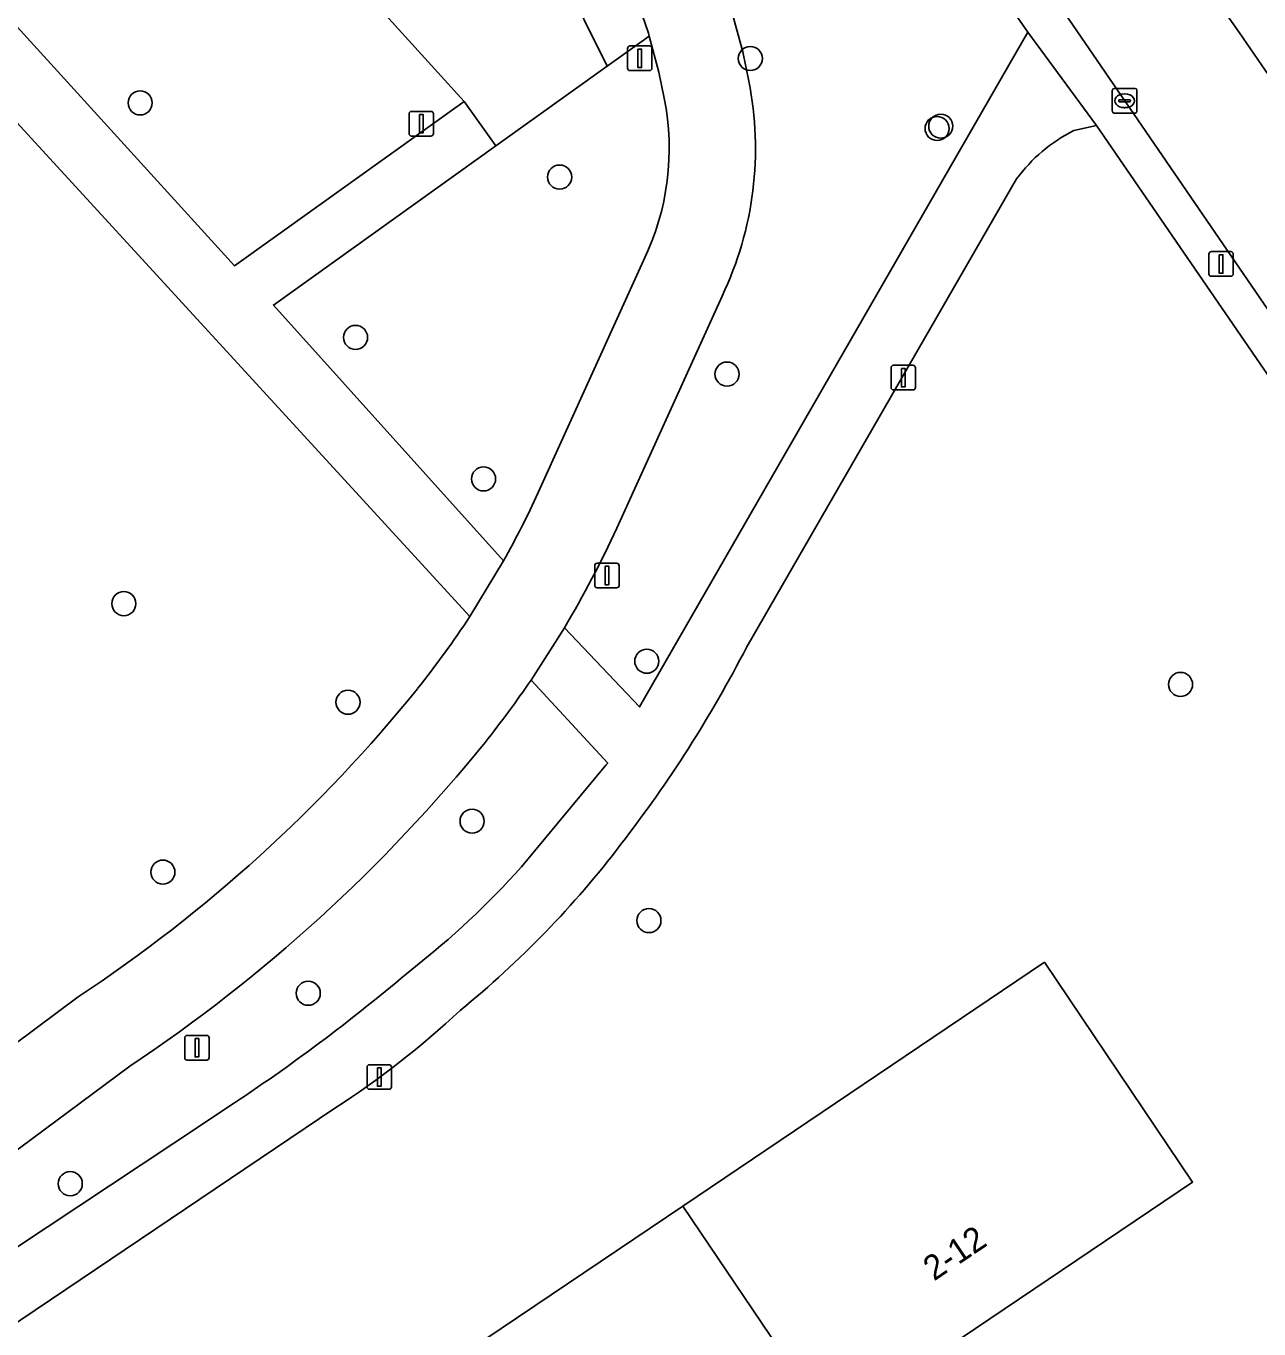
# Model space of a CAD drawing. Extents: x 157445 to 158888, y 383061 to 384688.
# Drawn here: x 158011.8 to 158061.8, y 383792.9 to 383845.7 of the extents above; entities that cross this region are included whole.
import ezdxf

# ---------------------------------------------------------------- set-up
doc = ezdxf.new("R2010")
doc.units = 0
for name, color, linetype in [('IMGEO_Boom', 7, 'Continuous'), ('IMGEO_Erf', 7, 'Continuous'), ('IMGEO_Fietspad_gesloten', 7, 'Continuous'), ('IMGEO_Groenvoorziening', 7, 'Continuous'), ('IMGEO_Kolk', 7, 'Continuous'), ('IMGEO_Lichtmast', 7, 'Continuous'), ('IMGEO_Pand', 7, 'Continuous'), ('IMGEO_Pand_nummerreeks', 7, 'Continuous'), ('IMGEO_Parkeervlak_halfverhard', 7, 'Continuous'), ('IMGEO_Rijbaan_lokaal_open', 7, 'Continuous'), ('IMGEO_Verkeersbordpaal', 7, 'Continuous'), ('IMGEO_Voetpad_halfverhard', 7, 'Continuous'), ('IMGEO_Voetpad_open', 7, 'Continuous')]:
    doc.layers.add(name, color=color, linetype=linetype)

msp = doc.modelspace()

# ---------------------------------------------------------------- linework, layer by layer
at = {"layer": 'IMGEO_Boom'}
for centre in [(158041.174, 383844.421), (158016.406, 383842.618), (158048.756, 383841.58), (158048.904, 383841.675), (158033.433, 383839.609), (158025.148, 383833.101), (158040.228, 383831.612), (158030.344, 383827.358), (158015.742, 383822.296), (158036.97, 383819.96), (158058.638, 383819.017), (158024.842, 383818.296), (158029.879, 383813.467), (158017.327, 383811.399), (158037.058, 383809.432), (158023.229, 383806.483), (158013.568, 383798.755)]:
    msp.add_circle(centre, 0.489, dxfattribs=at)
at = {"layer": 'IMGEO_Erf'}
for points in [[(158060.03, 383782.536), (158082.832, 383758.412), (158085.424, 383755.713), (158088.408, 383752.514), (158088.915, 383752.071), (158105.231, 383764.526), (158106, 383767.404), (158102.476, 383772.768), (158100.515, 383775.638), (158094.613, 383784.183), (158087.372, 383794.797), (158083.723, 383800.172), (158081.57, 383803.343), (158055.225, 383841.708), (158054.299, 383841.496)], [(158051.984, 383839.533), (158041.029, 383820.543)], [(158024.305, 383801.814), (158000, 383785.453), (157999.153, 383784.533), (157998.291, 383783.202)]]:
    msp.add_lwpolyline(points, dxfattribs=at)
msp.add_lwpolyline([(158015.062, 383769.115), (158009.046, 383778.039), (158023.723, 383787.933), (158038.433, 383797.849), (158053.11, 383807.743), (158059.126, 383798.819), (158044.449, 383788.925), (158029.739, 383779.009)], close=True, dxfattribs=at)
for centre, radius, start, end in [((158057.249, 383835.671), 6.53, 116.8567, 143.7357), ((157994.906, 383844.306), 51.884, 322.2325, 332.7419), ((158004.267, 383836.643), 39.793, 309.1569, 322.6997), ((158004.616, 383832.279), 36.274, 302.8736, 313.085)]:
    msp.add_arc(centre, radius, start, end, dxfattribs=at)
at = {"layer": 'IMGEO_Fietspad_gesloten'}
for points in [[(158041.113, 383843.504), (158040.866, 383844.685), (158040.388, 383846.467), (158038.631, 383851.59), (158038.302, 383852.55), (158037.804, 383854.078), (158037.479, 383855.23), (158037.196, 383856.757), (158036.877, 383858.474)], [(158033.429, 383857.768), (158034.07, 383854.425), (158034.435, 383853.129), (158034.991, 383851.415), (158035.77, 383849.143), (158037.038, 383845.445), (158037.07, 383845.326), (158037.46, 383843.872), (158037.681, 383842.817)], [(158036.837, 383836.222), (158032.565, 383826.808)], [(158035.752, 383825.362), (158040.026, 383834.777)], [(158031.155, 383824.033), (158029.788, 383821.778)], [(158032.271, 383819.193), (158033.627, 383821.318)], [(158013.887, 383806.337), (158007.796, 383801.81), (158004.921, 383799.673), (158000.029, 383796.035)], [(158002.118, 383793.226), (158007.009, 383796.864), (158015.982, 383803.527)]]:
    msp.add_lwpolyline(points, dxfattribs=at)
for centre, radius, start, end in [((158027.468, 383840.772), 13.916, 334.4792, 11.3208), ((158027.462, 383840.773), 10.421, 334.105, 11.3093), ((157997.631, 383842.812), 38.426, 330.7432, 335.3858), ((157997.392, 383842.939), 42.195, 329.1763, 335.3826), ((157997.521, 383842.868), 38.547, 321.4497, 326.8308), ((157997.9, 383842.601), 41.585, 321.4129, 325.7442), ((157980.301, 383857.187), 60.941, 303.44446, 321.01097), ((157980.342, 383857.142), 64.38, 303.61367, 321.04315)]:
    msp.add_arc(centre, radius, start, end, dxfattribs=at)
at = {"layer": 'IMGEO_Groenvoorziening'}
for points in [[(157947.808, 383908.446), (157904.241, 383852.492), (157897.07, 383843.386), (157895.489, 383841.379), (157893.132, 383838.504), (157893.585, 383835.721), (157894.56, 383834.399), (157906.358, 383817.738), (157931.737, 383782.008), (157938.042, 383786.453), (157940.085, 383787.894), (157959.052, 383779.967), (157966.816, 383785.159), (157989.251, 383803.05), (157991.638, 383803.565), (157993.23, 383803.909), (158000, 383802.934), (158007.796, 383801.81), (158013.887, 383806.337)], [(158052.445, 383845.49), (158047.404, 383852.735), (158045.178, 383856.038), (158038.631, 383851.59), (158040.388, 383846.467), (158040.866, 383844.685), (158041.113, 383843.504)], [(158029.788, 383821.778), (158000, 383854.238)], [(158033.627, 383821.318), (158036.68, 383818.102), (158052.445, 383845.49)], [(158037.681, 383842.817), (158037.46, 383843.872), (158037.07, 383845.326), (158035.363, 383844.105), (158030.845, 383840.874), (158021.815, 383834.415), (158031.155, 383824.033)], [(158032.565, 383826.808), (158036.837, 383836.222)], [(158040.026, 383834.777), (158035.752, 383825.362)], [(158031.889, 383811.619), (158035.303, 383815.741), (158035.385, 383815.817), (158032.271, 383819.193)], [(158015.982, 383803.527), (158007.009, 383796.864), (158010.08, 383795.309), (158017.731, 383800.376), (158020.24, 383802.038)]]:
    msp.add_lwpolyline(points, dxfattribs=at)
for points in [[(158029.555, 383842.669), (158000, 383875.224), (157994.843, 383880.905), (157992.039, 383878.385), (157986.327, 383873.253), (158000, 383858.247), (158020.237, 383836.007)], [(158035.77, 383849.143), (158034.406, 383848.41), (158033.481, 383847.913), (158035.363, 383844.105), (158037.07, 383845.326), (158037.038, 383845.445)]]:
    msp.add_lwpolyline(points, close=True, dxfattribs=at)
for centre, radius, start, end in [((158027.468, 383840.772), 13.916, 334.4792, 11.3208), ((158027.462, 383840.773), 10.421, 334.105, 11.3093), ((157997.631, 383842.812), 38.426, 330.7432, 335.3858), ((157997.392, 383842.939), 42.195, 329.1763, 335.3826), ((157997.521, 383842.868), 38.547, 321.4497, 326.8308), ((157997.9, 383842.601), 41.585, 321.4129, 325.7442), ((157980.301, 383857.187), 60.941, 303.44446, 321.01097), ((157980.342, 383857.142), 64.38, 303.61367, 321.04315), ((158006.732, 383834.076), 33.722, 307.8632, 318.2455), ((157978.135, 383865.426), 76.097, 303.59394, 310.37501)]:
    msp.add_arc(centre, radius, start, end, dxfattribs=at)
at = {"layer": 'IMGEO_Kolk'}
for p, q in [((158055.868, 383842.279), (158055.868, 383843.131)), ((158055.943, 383843.205), (158056.795, 383843.205)), ((158056.356, 383842.985), (158056.381, 383842.985)), ((158056.869, 383843.131), (158056.869, 383842.279)), ((158056.127, 383842.699), (158056.127, 383842.711)), ((158056.565, 383842.662), (158056.167, 383842.662)), ((158056.17, 383842.748), (158056.568, 383842.748)), ((158056.379, 383842.425), (158056.354, 383842.425)), ((158056.611, 383842.711), (158056.611, 383842.699)), ((158056.795, 383842.205), (158055.943, 383842.205))]:
    msp.add_line(p, q, dxfattribs=at)
for points in [[(158055.868, 383842.279), (158055.868, 383843.131)], [(158055.943, 383843.205), (158056.795, 383843.205)], [(158056.869, 383843.131), (158056.869, 383842.279)], [(158056.795, 383842.205), (158055.943, 383842.205)]]:
    msp.add_lwpolyline(points, dxfattribs=at)
for centre, radius, start, end in [((158055.945, 383843.129), 0.0765, 91.552, 178.448), ((158055.945, 383843.129), 0.0765, 91.552, 178.448), ((158056.793, 383843.129), 0.0765, 1.552, 88.448), ((158056.793, 383843.129), 0.0765, 1.552, 88.448), ((158055.945, 383842.281), 0.0765, 181.552, 268.448), ((158055.945, 383842.281), 0.0765, 181.552, 268.448), ((158056.167, 383842.708), 0.0403, 85.8775, 175.7526), ((158056.164, 383842.698), 0.0366, 178.938, 274.7102), ((158056.568, 383842.705), 0.043, 264.8664, 352.4533), ((158056.572, 383842.71), 0.0386, 1.7309, 96.639), ((158056.793, 383842.281), 0.0765, 271.552, 358.448), ((158056.793, 383842.281), 0.0765, 271.552, 358.448)]:
    msp.add_arc(centre, radius, start, end, dxfattribs=at)
for centre, major_axis, ratio, start_param, end_param in [((158056.355, 383842.705), (-0.387, 0.002), 0.722429, 4.712389, 7.853982), ((158056.38, 383842.705), (-0.39, 0.002), 0.717154, 1.570796, 4.712389)]:
    msp.add_ellipse(centre, major_axis=major_axis, ratio=ratio, start_param=start_param, end_param=end_param, dxfattribs=at)
at = {"layer": 'IMGEO_Lichtmast'}
for p, q in [((158036.289, 383844.93), (158037.079, 383844.93)), ((158037.079, 383844.93), (158036.289, 383844.93)), ((158036.189, 383844.03), (158036.189, 383844.83)), ((158036.189, 383844.83), (158036.189, 383844.03)), ((158037.179, 383844.83), (158037.179, 383844.03)), ((158037.179, 383844.03), (158037.179, 383844.83)), ((158037.079, 383843.93), (158036.289, 383843.93)), ((158036.289, 383843.93), (158037.079, 383843.93)), ((158059.79, 383835.683), (158059.79, 383836.483)), ((158059.79, 383836.483), (158059.79, 383835.683)), ((158059.89, 383836.583), (158060.68, 383836.583)), ((158060.68, 383836.583), (158059.89, 383836.583)), ((158060.78, 383836.483), (158060.78, 383835.683)), ((158060.78, 383835.683), (158060.78, 383836.483)), ((158060.68, 383835.583), (158059.89, 383835.583)), ((158059.89, 383835.583), (158060.68, 383835.583)), ((158046.886, 383831.069), (158046.886, 383831.869)), ((158046.886, 383831.869), (158046.886, 383831.069)), ((158046.986, 383831.969), (158047.776, 383831.969)), ((158047.776, 383831.969), (158046.986, 383831.969)), ((158047.876, 383831.869), (158047.876, 383831.069)), ((158047.876, 383831.069), (158047.876, 383831.869)), ((158047.776, 383830.969), (158046.986, 383830.969)), ((158046.986, 383830.969), (158047.776, 383830.969)), ((158034.857, 383823.037), (158034.857, 383823.837)), ((158034.857, 383823.837), (158034.857, 383823.037)), ((158034.957, 383823.937), (158035.747, 383823.937)), ((158035.747, 383823.937), (158034.957, 383823.937)), ((158035.847, 383823.837), (158035.847, 383823.037)), ((158035.847, 383823.037), (158035.847, 383823.837)), ((158035.747, 383822.937), (158034.957, 383822.937)), ((158034.957, 383822.937), (158035.747, 383822.937)), ((158018.316, 383804.772), (158019.106, 383804.772)), ((158019.106, 383804.772), (158018.316, 383804.772)), ((158018.216, 383803.872), (158018.216, 383804.672)), ((158018.216, 383804.672), (158018.216, 383803.872)), ((158019.206, 383804.672), (158019.206, 383803.872)), ((158019.206, 383803.872), (158019.206, 383804.672)), ((158019.106, 383803.772), (158018.316, 383803.772)), ((158018.316, 383803.772), (158019.106, 383803.772)), ((158025.616, 383802.685), (158025.616, 383803.485)), ((158025.616, 383803.485), (158025.616, 383802.685)), ((158025.716, 383803.585), (158026.506, 383803.585)), ((158026.506, 383803.585), (158025.716, 383803.585)), ((158026.606, 383803.485), (158026.606, 383802.685)), ((158026.606, 383802.685), (158026.606, 383803.485)), ((158026.506, 383802.585), (158025.716, 383802.585)), ((158025.716, 383802.585), (158026.506, 383802.585))]:
    msp.add_line(p, q, dxfattribs=at)
for points in [[(158036.609, 383844.805), (158036.759, 383844.805), (158036.759, 383844.055), (158036.609, 383844.055), (158036.609, 383844.805)], [(158060.21, 383836.458), (158060.36, 383836.458), (158060.36, 383835.708), (158060.21, 383835.708), (158060.21, 383836.458)], [(158047.306, 383831.844), (158047.456, 383831.844), (158047.456, 383831.094), (158047.306, 383831.094), (158047.306, 383831.844)], [(158035.277, 383823.812), (158035.427, 383823.812), (158035.427, 383823.062), (158035.277, 383823.062), (158035.277, 383823.812)], [(158018.636, 383804.647), (158018.786, 383804.647), (158018.786, 383803.897), (158018.636, 383803.897), (158018.636, 383804.647)], [(158026.036, 383803.46), (158026.186, 383803.46), (158026.186, 383802.71), (158026.036, 383802.71), (158026.036, 383803.46)]]:
    msp.add_lwpolyline(points, dxfattribs=at)
for centre, start, end in [((158036.289, 383844.83), 90, 180), ((158036.289, 383844.83), 90, 180), ((158037.079, 383844.83), 0, 90), ((158037.079, 383844.83), 360, 90), ((158036.289, 383844.03), 180, 270), ((158036.289, 383844.03), 180, 270), ((158037.079, 383844.03), 270, 0), ((158037.079, 383844.03), 270, 0), ((158059.89, 383836.483), 90, 180), ((158059.89, 383836.483), 90, 180), ((158060.68, 383836.483), 0, 90), ((158060.68, 383836.483), 360, 90), ((158059.89, 383835.683), 180, 270), ((158059.89, 383835.683), 180, 270), ((158060.68, 383835.683), 270, 0), ((158060.68, 383835.683), 270, 0), ((158046.986, 383831.869), 90, 180), ((158046.986, 383831.869), 90, 180), ((158047.776, 383831.869), 0, 90), ((158047.776, 383831.869), 360, 90), ((158046.986, 383831.069), 180, 270), ((158046.986, 383831.069), 180, 270), ((158047.776, 383831.069), 270, 0), ((158047.776, 383831.069), 270, 0), ((158034.957, 383823.837), 90, 180), ((158034.957, 383823.837), 90, 180), ((158035.747, 383823.837), 0, 90), ((158035.747, 383823.837), 360, 90), ((158034.957, 383823.037), 180, 270), ((158034.957, 383823.037), 180, 270), ((158035.747, 383823.037), 270, 0), ((158035.747, 383823.037), 270, 0), ((158018.316, 383804.672), 90, 180), ((158018.316, 383804.672), 90, 180), ((158019.106, 383804.672), 0, 90), ((158019.106, 383804.672), 360, 90), ((158018.316, 383803.872), 180, 270), ((158018.316, 383803.872), 180, 270), ((158019.106, 383803.872), 270, 0), ((158019.106, 383803.872), 270, 0), ((158025.716, 383803.485), 90, 180), ((158025.716, 383803.485), 90, 180), ((158026.506, 383803.485), 0, 90), ((158026.506, 383803.485), 360, 90), ((158025.716, 383802.685), 180, 270), ((158025.716, 383802.685), 180, 270), ((158026.506, 383802.685), 270, 0), ((158026.506, 383802.685), 270, 0)]:
    msp.add_arc(centre, 0.1, start, end, dxfattribs=at)
at = {"layer": 'IMGEO_Pand'}
for points in [[(158044.449, 383788.925), (158059.126, 383798.819), (158053.11, 383807.743), (158038.433, 383797.849)], [(158029.739, 383779.009), (158044.449, 383788.925), (158038.433, 383797.849), (158023.723, 383787.933)]]:
    msp.add_lwpolyline(points, close=True, dxfattribs=at)
at = {"layer": 'IMGEO_Parkeervlak_halfverhard'}
msp.add_lwpolyline([(158003.296, 383888.217), (158004.698, 383889.468), (158003.276, 383891.048), (158001.192, 383893.195), (158000, 383892.164), (157988.783, 383882.458), (157990.726, 383879.963), (157992.039, 383878.385), (157994.843, 383880.905), (158000, 383875.224), (158029.555, 383842.669), (158030.845, 383840.874), (158035.363, 383844.105), (158033.481, 383847.913), (158034.406, 383848.41), (158035.77, 383849.143), (158034.991, 383851.415), (158034.435, 383853.129), (158034.07, 383854.425), (158027.176, 383862.004)], close=True, dxfattribs=at)
at = {"layer": 'IMGEO_Rijbaan_lokaal_open'}
msp.add_lwpolyline([(158065.725, 383838.686), (158064.752, 383840.047), (158061.029, 383845.468), (158060.097, 383846.787), (158051.041, 383860.044), (158046.539, 383857.088), (158048.821, 383853.725), (158082.795, 383804.174), (158086.592, 383798.626), (158086.867, 383798.223), (158091.359, 383801.235), (158082.929, 383813.621), (158081.856, 383815.068)], close=True, dxfattribs=at)
at = {"layer": 'IMGEO_Verkeersbordpaal'}
for p, q in [((158027.421, 383842.273), (158028.211, 383842.273)), ((158028.211, 383842.273), (158027.421, 383842.273)), ((158027.321, 383841.373), (158027.321, 383842.173)), ((158027.321, 383842.173), (158027.321, 383841.373)), ((158028.311, 383842.173), (158028.311, 383841.373)), ((158028.311, 383841.373), (158028.311, 383842.173)), ((158028.211, 383841.273), (158027.421, 383841.273)), ((158027.421, 383841.273), (158028.211, 383841.273))]:
    msp.add_line(p, q, dxfattribs=at)
msp.add_lwpolyline([(158027.741, 383842.148), (158027.891, 383842.148), (158027.891, 383841.398), (158027.741, 383841.398), (158027.741, 383842.148)], dxfattribs=at)
for centre, start, end in [((158027.421, 383842.173), 90, 180), ((158027.421, 383842.173), 90, 180), ((158028.211, 383842.173), 0, 90), ((158028.211, 383842.173), 360, 90), ((158027.421, 383841.373), 180, 270), ((158027.421, 383841.373), 180, 270), ((158028.211, 383841.373), 270, 0), ((158028.211, 383841.373), 270, 0)]:
    msp.add_arc(centre, 0.1, start, end, dxfattribs=at)
at = {"layer": 'IMGEO_Voetpad_halfverhard'}
for points in [[(157960.982, 383897.155), (158000, 383854.238), (158029.788, 383821.778), (158031.155, 383824.033), (158021.815, 383834.415), (158030.845, 383840.874), (158029.555, 383842.669), (158020.237, 383836.007), (158000, 383858.247), (157986.327, 383873.253), (157992.039, 383878.385), (157990.726, 383879.963), (157984.977, 383874.772), (157966.606, 383894.786)], [(158054.299, 383841.496), (158055.225, 383841.708), (158052.445, 383845.49), (158036.68, 383818.102), (158033.627, 383821.318), (158032.271, 383819.193), (158035.385, 383815.817), (158035.303, 383815.741), (158031.889, 383811.619)], [(158041.029, 383820.543), (158051.984, 383839.533)], [(158020.24, 383802.038), (158017.731, 383800.376), (158010.08, 383795.309), (158003.297, 383790.817), (157998.077, 383787.225), (157997.244, 383786.47)], [(157998.291, 383783.202), (157999.153, 383784.533), (158000, 383785.453), (158024.305, 383801.814)]]:
    msp.add_lwpolyline(points, dxfattribs=at)
for centre, radius, start, end in [((158057.249, 383835.671), 6.53, 116.8567, 143.7357), ((157994.906, 383844.306), 51.884, 322.2325, 332.7419), ((158004.267, 383836.643), 39.793, 309.1569, 322.6997), ((158006.732, 383834.076), 33.722, 307.8632, 318.2455), ((157978.135, 383865.426), 76.097, 303.59394, 310.37501), ((158004.616, 383832.279), 36.274, 302.8736, 313.085)]:
    msp.add_arc(centre, radius, start, end, dxfattribs=at)
at = {"layer": 'IMGEO_Voetpad_open'}
for points in [[(158048.821, 383853.725), (158047.404, 383852.735), (158052.445, 383845.49), (158055.225, 383841.708), (158081.57, 383803.343), (158083.723, 383800.172), (158087.372, 383794.797), (158094.613, 383784.183), (158100.515, 383775.638), (158102.476, 383772.768), (158106, 383767.404), (158108.003, 383764.524)], [(158106.811, 383769.02), (158103.888, 383773.339), (158101.97, 383775.986), (158098.261, 383781.605), (158089.558, 383794.264), (158086.867, 383798.223), (158086.592, 383798.626), (158082.795, 383804.174), (158048.821, 383853.725)], [(158060.097, 383846.787), (158061.029, 383845.468), (158064.752, 383840.047), (158066.108, 383840.94), (158067.267, 383839.308), (158083.034, 383816.347), (158084.481, 383814.188), (158097.193, 383795.752), (158098.433, 383793.965), (158097.04, 383792.967), (158099.105, 383789.878), (158099.211, 383789.817)]]:
    msp.add_lwpolyline(points, dxfattribs=at)

# ---------------------------------------------------------------- texts
at = {"layer": 'IMGEO_Pand_nummerreeks'}
msp.add_text('2-12', height=1, rotation=33.9843, dxfattribs=at).set_placement((158048.63, 383794.783))

doc.saveas('drawing.dxf')
